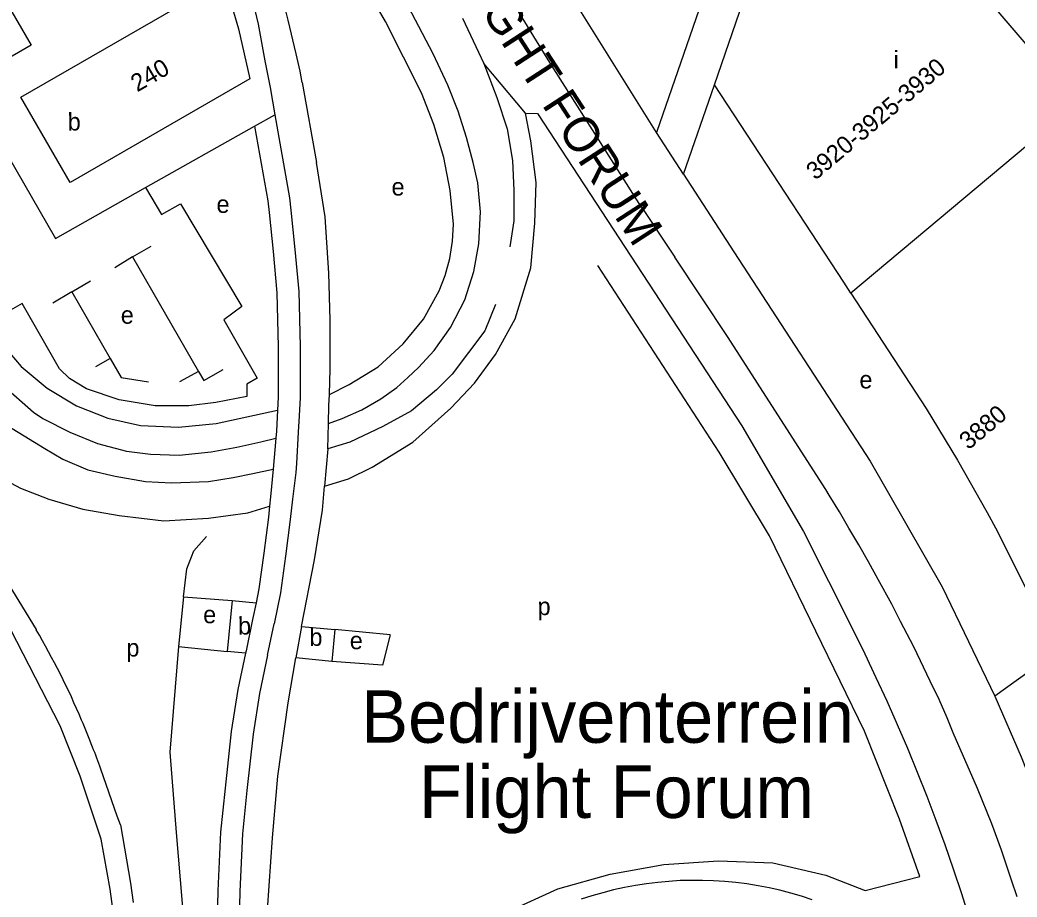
# Model space of a CAD drawing. Extents: x 154765 to 156627, y 383996 to 386132.
# Drawn here: x 155994.8 to 156222.1, y 384700.7 to 384900.8 of the extents above; entities that cross this region are included whole.
import ezdxf

# ---------------------------------------------------------------- set-up
doc = ezdxf.new("R2010")
doc.units = 0
for name, color, linetype in [('BLT_Basislijn', 7, 'Continuous'), ('BLT_Bebouwing', 7, 'Continuous'), ('BLT_Centroide', 7, 'Continuous'), ('BLT_Huisnummer', 7, 'Continuous'), ('BLT_Huisnummer_reeks', 7, 'Continuous'), ('BLT_Onderverdeling_panden', 7, 'Continuous'), ('BLT_Sport_parknaam', 7, 'Continuous'), ('BLT_Straatnaam_hoofdweg', 7, 'Continuous'), ('BLT_Vlakafsluiter', 7, 'Continuous')]:
    doc.layers.add(name, color=color, linetype=linetype)

msp = doc.modelspace()

# ---------------------------------------------------------------- linework, layer by layer
at = {"layer": 'BLT_Basislijn'}
for p, q in [((156055.98, 384900.79), (156053.29, 384911.26)), ((156047.31, 384907.37), (156049.11, 384899.9)), ((156095.68, 384901.22), (156100.52, 384890.92)), ((156049.11, 384899.9), (156050.6, 384891.52)), ((156057.75, 384893.14), (156055.98, 384900.79)), ((156058.67, 384889.13), (156057.75, 384893.14)), ((156050.6, 384891.52), (156051.83, 384885.39)), ((156100.52, 384890.92), (156103.51, 384883.15)), ((156059.17, 384886.55), (156058.67, 384889.13)), ((156051.83, 384885.39), (156052.92, 384879.18)), ((156059.17, 384886.55), (156062.39, 384868.29)), ((156146.05, 384865.68), (156153.18, 384886)), ((156103.51, 384883.15), (156105.9, 384875.97)), ((156110.09, 384879.56), (156112.8, 384879.51)), ((156111.28, 384873.28), (156110.09, 384879.56)), ((156023.43, 384862.57), (156048.3, 384876.58)), ((156105.9, 384875.97), (156107.1, 384868.79)), ((156146.05, 384865.68), (156139.91, 384875.13)), ((156112.48, 384863.71), (156111.28, 384873.28)), ((156064.35, 384855.93), (156062.39, 384868.29)), ((156107.1, 384868.79), (156107.4, 384861.91)), ((156112.18, 384854.43), (156112.48, 384863.71)), ((156107.4, 384861.91), (156107.4, 384855.03)), ((156136, 384858.96), (156144.12, 384846.73)), ((156065.25, 384843.07), (156064.35, 384855.93)), ((156107.4, 384855.03), (156106.5, 384849.05)), ((156111.28, 384844.26), (156112.18, 384854.43)), ((156020.42, 384846.78), (156024.7, 384849.22)), ((156020.42, 384846.78), (156016.39, 384844.3)), ((156020.42, 384846.78), (156035.52, 384820.63)), ((156107.7, 384832.6), (156111.28, 384844.26)), ((156065.55, 384832.3), (156065.25, 384843.07)), ((156006.63, 384838.83), (156010.89, 384841.28)), ((156006.63, 384838.83), (156002.26, 384836.22)), ((156006.63, 384838.83), (156015.36, 384823.6)), ((156103.21, 384835.89), (156100.82, 384829.91)), ((156065.55, 384821.23), (156065.55, 384832.3)), ((156103.21, 384824.52), (156107.7, 384832.6)), ((156100.82, 384829.91), (156093.35, 384820.04)), ((156015.36, 384823.6), (156012.02, 384821.66)), ((156015.36, 384823.6), (156017.87, 384819.23)), ((156098.43, 384817.94), (156103.21, 384824.52)), ((156017.87, 384819.23), (156024.08, 384818.26)), ((156035.52, 384820.63), (156031.16, 384818.28)), ((156065.34, 384815.35), (156065.55, 384821.23)), ((156093.35, 384820.04), (156089.76, 384816.45)), ((156093.05, 384812.26), (156098.43, 384817.94)), ((156065.25, 384812.86), (156065.34, 384815.35)), ((156089.76, 384816.45), (156084.08, 384811.66)), ((156065.12, 384808.73), (156065.25, 384812.86)), ((156084.38, 384804.49), (156093.05, 384812.26)), ((155987.12, 384811.23), (156000.44, 384803.04)), ((156084.08, 384811.66), (156077.5, 384808.07)), ((156064.95, 384802.99), (156065.12, 384808.73)), ((156077.5, 384808.07), (156070.03, 384804.49)), ((156058.26, 384806.76), (156057.88, 384799.62)), ((156070.03, 384804.49), (156064.95, 384802.99)), ((156075.11, 384798.8), (156084.38, 384804.49)), ((156000.44, 384803.04), (156004.57, 384800.6)), ((156064.95, 384802.99), (156064.22, 384794.46)), ((156004.57, 384800.6), (156010.24, 384798.21)), ((156069.73, 384796.11), (156075.11, 384798.8)), ((156010.24, 384798.21), (156016.52, 384796.71)), ((156016.52, 384796.71), (156023.4, 384795.51)), ((156037.75, 384795.51), (156043.43, 384796.41)), ((156043.43, 384796.41), (156047.91, 384797.31)), ((156047.91, 384797.31), (156052.5, 384798.33)), ((156023.4, 384795.51), (156029.38, 384795.21)), ((156029.38, 384795.21), (156037.75, 384795.51)), ((156063.75, 384788.99), (156064.22, 384794.46)), ((156064.22, 384794.46), (156069.73, 384796.11)), ((156046.71, 384788.34), (156051.72, 384789.92)), ((156017.42, 384787.74), (156027.58, 384786.54)), ((156037.75, 384787.14), (156046.71, 384788.34)), ((156061.96, 384777.63), (156063.75, 384788.99)), ((156027.58, 384786.54), (156037.75, 384787.14)), ((156059.02, 384762.44), (156061.96, 384777.63)), ((156032.07, 384769.22), (156030.93, 384757.84)), ((156032.07, 384769.22), (156043.16, 384768.38)), ((156079.19, 384760.52), (156066.62, 384761.72)), ((156079.19, 384760.52), (156077.47, 384753.64)), ((156030.93, 384757.84), (156042.06, 384756.75)), ((156231.21, 384756.8), (156217.06, 384746.54)), ((156055.98, 384745.03), (156057.72, 384755.25)), ((156077.47, 384753.64), (156065.92, 384754.47)), ((156053.59, 384728.28), (156055.98, 384745.03)), ((156013.27, 384713.9), (156008.49, 384728.25)), ((156052.39, 384714.22), (156053.59, 384728.28)), ((156017.68, 384717.16), (156020.01, 384703.9)), ((156015.36, 384702.5), (156013.27, 384713.9)), ((156051.2, 384697.77), (156052.39, 384714.22)), ((156020.01, 384703.9), (156020.62, 384699.44)), ((156016.28, 384695.72), (156015.36, 384702.5))]:
    msp.add_line(p, q, dxfattribs=at)
for points in [[(156136, 384858.96), (156115.57, 384891.11), (156096.29, 384922.61), (156080.28, 384952.51), (156069.18, 384974.46), (156063, 384988.46), (156057.67, 385001.26), (156052.62, 385013.66), (156046.98, 385030.26), (156042.75, 385043.48)], [(156164.06, 384945.15), (156139.91, 384875.13)], [(156065.34, 384815.35), (156069.84, 384817.65), (156076.45, 384821.69), (156082.14, 384826.94), (156086.82, 384832.59), (156090.38, 384838.99), (156091.74, 384842.55), (156092.79, 384846.44), (156093.42, 384850.35), (156093.66, 384854.23), (156092.91, 384861.91), (156091.4, 384869.47), (156089.18, 384876.95), (156086.34, 384884.21), (156078.11, 384900.51), (156063.66, 384925.43), (156056.1, 384941.52)], [(156139.91, 384875.13), (156105.37, 384930.61)], [(155947.12, 384899.61), (155947.5, 384901.16), (155977.2, 384918.58), (155983.01, 384919.78), (155997.35, 384895.09), (155982.3, 384886.45), (155983.87, 384882.97), (155964.19, 384869.82)], [(156065.12, 384808.73), (156068.28, 384809.86), (156072.74, 384811.9), (156077.06, 384814.37), (156080.72, 384816.98), (156083.19, 384819.23), (156085.66, 384821.55), (156089.25, 384825.39), (156092.98, 384830.65), (156096.25, 384837), (156098.3, 384843.44), (156099.4, 384849.73), (156099.76, 384857.06), (156099.15, 384863.66), (156098.1, 384868.29), (156096.61, 384874.03), (156094.72, 384880.02), (156092.36, 384885.93), (156089.03, 384893.14), (156084.11, 384902.36), (156083.82, 384902.9)], [(155970.97, 384868.46), (155986.8, 384878.86), (156002.87, 384850.99), (156023.43, 384862.57)], [(156048.3, 384876.58), (156052.92, 384879.18)], [(156052.92, 384879.18), (156056.24, 384860.27), (156056.58, 384857.42), (156057.48, 384848.45), (156058.37, 384838.88), (156058.67, 384826.32), (156058.67, 384814.65), (156058.45, 384810.47), (156058.26, 384806.76)], [(156112.8, 384879.51), (156159.36, 384808.24), (156173.42, 384784.11), (156184.81, 384761.44)], [(156048.3, 384876.58), (156051.29, 384859.54), (156051.61, 384856.88), (156052.5, 384847.97), (156053.38, 384838.59), (156053.67, 384826.26), (156053.67, 384814.79), (156053.51, 384811.77)], [(156023.43, 384862.57), (156027.07, 384856.44), (156031.38, 384858.87), (156045.39, 384835.44), (156041.27, 384832.4), (156048.9, 384819.1), (156046.53, 384817.73), (156046.55, 384814.94), (156039.42, 384813.54), (156033.28, 384812.76), (156025.61, 384812.76), (156017.41, 384814.12), (156009.98, 384816.64), (156006.07, 384819.03), (156003.77, 384821.25), (155995.3, 384836.12), (155991.05, 384833.74), (155970.97, 384868.46)], [(155966.85, 384865.29), (155977.34, 384847.26), (155985.46, 384834.23), (155988.81, 384829.4), (155991.2, 384826.31), (155995.09, 384821.78), (156001.03, 384816.78), (156007.69, 384812.8), (156014.81, 384809.96), (156022.3, 384808.27), (156030.91, 384807.9), (156039.49, 384808.74), (156053.51, 384811.77)], [(156146.05, 384865.68), (156157.57, 384847.96), (156188.64, 384800.15), (156205.09, 384771.5), (156217.06, 384746.54)], [(155963.85, 384858.14), (155976.36, 384836.75), (155982.06, 384827.68), (155990.84, 384817.59), (155997.87, 384811.31), (156000, 384809.93), (156006.15, 384806.79), (156012.47, 384804.16), (156019.06, 384802.43), (156024.57, 384801.78), (156031.1, 384801.56), (156038.42, 384802.32), (156044.23, 384803.38), (156049.74, 384804.57), (156053.13, 384805.44)], [(156222.16, 384700.72), (156220.87, 384704.59), (156218.59, 384711.39), (156216.34, 384717.39), (156213.13, 384725.45), (156207.59, 384738.16), (156206.2, 384741.58), (156204.35, 384745.8), (156202.33, 384749.98), (156198.6, 384757.76), (156195.59, 384763.57), (156193.57, 384767.53), (156190.46, 384773.19), (156188.24, 384777.21), (156186.04, 384781.04), (156183.76, 384784.85), (156181.64, 384788.6), (156179.28, 384792.41), (156178.53, 384793.68), (156177, 384796.09), (156156.27, 384828.4), (156144.12, 384846.73)], [(156066.37, 384651.6), (156071.21, 384663.04), (156077.65, 384673.68), (156086.03, 384682.85), (156095.55, 384690.85), (156106.1, 384697.42), (156117.43, 384702.54), (156129.38, 384705.93), (156141.61, 384708.16), (156154.02, 384708.97), (156166.44, 384708.53), (156178.54, 384705.69), (156187.51, 384702.21), (156199.99, 384705.41), (156195.34, 384718.5), (156187.31, 384738.53), (156176.24, 384761.35), (156165.68, 384783.11), (156154.18, 384802.19), (156126.58, 384844.77)], [(156035.52, 384820.63), (156036.7, 384818.57), (156041.09, 384821.08)], [(156053.51, 384811.77), (156053.26, 384807.02), (156053.13, 384805.44)], [(156053.13, 384805.44), (156052.5, 384798.33)], [(155978.85, 384803.32), (155989.28, 384796.96), (155994.94, 384794), (156001.39, 384791.48), (156009.15, 384789.21), (156009.15, 384789.21), (156017.42, 384787.74)], [(156057.88, 384799.62), (156057.67, 384797.61), (156056.92, 384791.46)], [(156008.49, 384728.25), (156003.96, 384739.77), (155991.3, 384764.52), (155976.03, 384788.73), (155971.5, 384796.52)], [(156052.5, 384798.33), (156051.95, 384792)], [(156051.95, 384792), (156051.72, 384789.92)], [(155980.29, 384791.35), (155998.48, 384761.75), (155998.51, 384761.7)], [(156051.72, 384789.92), (156051.45, 384787.42), (156050.4, 384779.13), (156049.26, 384771), (156048.62, 384767.87)], [(156056.92, 384791.46), (156056.42, 384786.84), (156055.36, 384778.47), (156054.19, 384770.15), (156052.73, 384763.03)], [(156032.07, 384769.22), (156032.87, 384775.62), (156034.42, 384779.72), (156037.31, 384783)], [(156048.62, 384767.87), (156047.83, 384764.04)], [(156047.83, 384764.04), (156046.37, 384756.91), (156046.25, 384756.35)], [(156184.81, 384761.44), (156187.42, 384756.16), (156189.95, 384750.83), (156192.41, 384745.48), (156194.8, 384740.09), (156197.12, 384734.67), (156199.36, 384729.22), (156201.52, 384723.73), (156203.62, 384718.22), (156205.63, 384712.68), (156207.58, 384707.12), (156209.44, 384701.53), (156211.23, 384695.91), (156212.95, 384690.27), (156214.58, 384684.61), (156216.14, 384678.93), (156217.62, 384673.22), (156219.03, 384667.5), (156219.83, 384664.1)], [(156030.93, 384757.84), (156028.96, 384733.75), (156030.39, 384715.44), (156033.16, 384683.02)], [(156046.25, 384756.35), (156044.49, 384748.03), (156042.98, 384738.5), (156041.58, 384725.51), (156040.53, 384715.49), (156039.92, 384702.13), (156039.62, 384688.85), (156039.62, 384677.94), (156040.11, 384663.77), (156040.72, 384654.55), (156042.13, 384644.85), (156043.35, 384635.49), (156045.19, 384627.74), (156047.27, 384617.95)], [(156051.26, 384755.87), (156049.4, 384747.12), (156047.94, 384737.84), (156046.55, 384724.99), (156045.52, 384715.12), (156044.92, 384701.96), (156044.62, 384688.8), (156044.62, 384678.03), (156045.1, 384664.02), (156045.7, 384655.08), (156047.09, 384645.54), (156048.28, 384636.39), (156050.07, 384628.84), (156052.05, 384619.5), (156054.24, 384610.75), (156056.62, 384603.24), (156060, 384592.51), (156062.01, 384587.28)], [(156217.06, 384746.54), (156223.08, 384732.73), (156229.96, 384715.21), (156237.53, 384692.35)], [(156017.68, 384717.16), (156016.99, 384719.18), (156013.2, 384729.91)], [(156175.42, 384700.1), (156172.99, 384700.89), (156170.54, 384701.61), (156168.07, 384702.24), (156165.58, 384702.8), (156163.07, 384703.29), (156160.55, 384703.69), (156158.02, 384704.01), (156155.48, 384704.26), (156152.93, 384704.42), (156150.38, 384704.51), (156147.83, 384704.51), (156145.28, 384704.44), (156142.73, 384704.28), (156140.19, 384704.05), (156137.66, 384703.73), (156135.14, 384703.34), (156132.63, 384702.87), (156130.14, 384702.32), (156127.66, 384701.69), (156125.21, 384700.98), (156122.78, 384700.2)]]:
    msp.add_lwpolyline(points, dxfattribs=at)
for centre, radius, start, end in [((155837.68, 384668.08), 186.09, 23.0949, 30.2041), ((155839.17, 384668.72), 184.47, 21.0291, 23.094), ((155842.57, 384669.88), 180.88, 19.3825, 21.0711)]:
    msp.add_arc(centre, radius, start, end, dxfattribs=at)
at = {"layer": 'BLT_Bebouwing'}
for p, q in [((156214.39, 384906.69), (156235.7, 384881.73)), ((156043.16, 384768.38), (156042.06, 384756.75)), ((156051.26, 384755.87), (156052.73, 384763.03)), ((156059.02, 384762.44), (156057.72, 384755.25)), ((156059.02, 384762.44), (156066.62, 384761.72)), ((156066.62, 384761.72), (156065.92, 384754.47)), ((156046.25, 384756.35), (156042.06, 384756.75)), ((156065.92, 384754.47), (156057.72, 384755.25))]:
    msp.add_line(p, q, dxfattribs=at)
for points in [[(156153.18, 384886), (156172.76, 384943.17), (156179.32, 384948.68)], [(156184.26, 384838.5), (156182.66, 384840.97), (156153.18, 384886)], [(156184.26, 384838.5), (156201.43, 384812.17), (156208.56, 384800.4), (156215.34, 384788.41), (156217.22, 384784.97), (156229.41, 384760.71), (156231.21, 384756.8)], [(156043.16, 384768.38), (156048.62, 384767.87)]]:
    msp.add_lwpolyline(points, dxfattribs=at)
msp.add_lwpolyline([(155994.96, 384883.21), (156041.37, 384910), (156044.59, 384898.79), (156047.23, 384887.42), (156006.21, 384863.74)], close=True, dxfattribs=at)
at = {"layer": 'BLT_Onderverdeling_panden'}
msp.add_line((156235.7, 384881.73), (156184.26, 384838.5), dxfattribs=at)
at = {"layer": 'BLT_Vlakafsluiter'}
msp.add_line((156110.09, 384879.56), (156100.52, 384890.92), dxfattribs=at)

# ---------------------------------------------------------------- texts
at = {"layer": 'BLT_Centroide'}
for s, p in [('i', (156193.97, 384889.77)), ('e', (156079.51, 384860.77)), ('e', (156039.61, 384856.81)), ('e', (156017.78, 384831.52)), ('e', (156186.19, 384816.76)), ('p', (156112.81, 384765.03)), ('e', (156036.56, 384763.18)), ('e', (156069.99, 384757.25)), ('p', (156019.06, 384755.57))]:
    msp.add_text(s, height=4, dxfattribs=at).set_placement(p)
for p in [(156005.71, 384875.59), (156044.55, 384760.57), (156060.82, 384757.98)]:
    msp.add_text('b', height=4, rotation=1, dxfattribs=at).set_placement(p)
at = {"layer": 'BLT_Huisnummer'}
for s, rotation, p in [('240', 29.9993, (156021.53, 384884.29)), ('3880', 40.0247, (156211.04, 384802.58))]:
    msp.add_text(s, height=4, rotation=rotation, dxfattribs=at).set_placement(p)
at = {"layer": 'BLT_Huisnummer_reeks'}
msp.add_text('3920-3925-3930', height=4, rotation=40.0408, dxfattribs=at).set_placement((156176.15, 384864.13))
at = {"layer": 'BLT_Sport_parknaam'}
for s, p in [('Bedrijventerrein', (156072.58, 384735.9)), ('Flight Forum', (156085.77, 384718.75))]:
    msp.add_text(s, height=12, dxfattribs=at).set_placement(p)
at = {"layer": 'BLT_Straatnaam_hoofdweg'}
msp.add_text('FLIGHT FORUM', height=8, rotation=303, dxfattribs=at).set_placement((156091.31, 384915.91))

doc.saveas('drawing.dxf')
